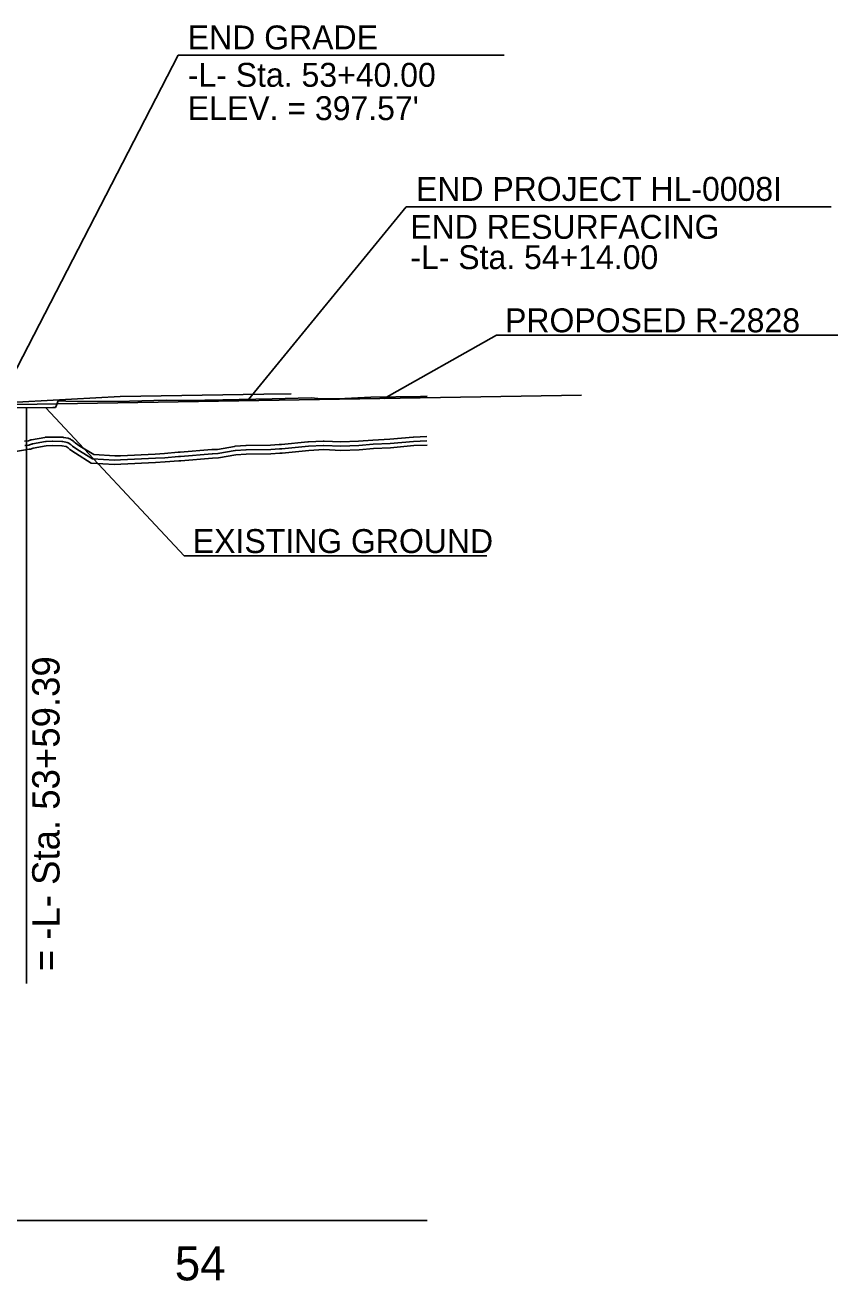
# Model space of a CAD drawing. Extents: x 1625686 to 1640492, y 1161393 to 1175642.
# Drawn here: x 1634553 to 1634790.9, y 1174893.1 to 1175260.6 of the extents above; entities that cross this region are included whole.
import ezdxf

# ---------------------------------------------------------------- set-up
doc = ezdxf.new("R2010")
doc.units = 0
for name, color, linetype in [('Exist Profile Cell', 7, 'Continuous'), ('Exist Vertical Profile Ground Line', 7, 'Continuous'), ('Exist Vertical Profile Horizontal Axis Label Major', 7, 'Continuous'), ('Prop PFL Text', 7, 'Continuous'), ('Prop VPI Label', 7, 'Continuous'), ('Scratch_Level_1', 7, 'Continuous'), ('Scratch_Level_3', 7, 'Continuous'), ('Scratch_Level_5', 7, 'Continuous'), ('Scratch_Level_7', 7, 'Continuous')]:
    doc.layers.add(name, color=color, linetype=linetype)

msp = doc.modelspace()

# ---------------------------------------------------------------- linework, layer by layer
at = {"layer": 'Exist Profile Cell'}
msp.add_line((1630204.31, 1174910.79), (1634670.63, 1174910.79), dxfattribs=at)
at = {"layer": 'Exist Vertical Profile Ground Line'}
msp.add_lwpolyline([(1634549.61, 1175148.68), (1634561.05, 1175148.7), (1634561.81, 1175148.73), (1634562.13, 1175149.43), (1634562.61, 1175150.67), (1634564.92, 1175150.56), (1634581.92, 1175150.48), (1634583.54, 1175150.64), (1634594.21, 1175150.87), (1634600.26, 1175150.79), (1634610.8, 1175150.96), (1634625.27, 1175151.27), (1634636.75, 1175151.62), (1634639.64, 1175151.3), (1634644.68, 1175151.25), (1634654.19, 1175151.73), (1634668.69, 1175151.94), (1634670.63, 1175152.03)], dxfattribs=at)
at = {"layer": 'Prop PFL Text'}
msp.add_line((1634553.35, 1174980.21), (1634553.35, 1175148.69), dxfattribs=at)
at = {"layer": 'Prop VPI Label'}
for p, q in [((1634545.73, 1175151), (1634597.75, 1175251.82)), ((1634597.75, 1175251.82), (1634693.23, 1175251.82)), ((1634618.31, 1175151.12), (1634664.56, 1175207.49)), ((1634664.56, 1175207.49), (1634788.92, 1175207.49)), ((1634599.55, 1175105.35), (1634558.98, 1175148.69)), ((1634688.15, 1175105.35), (1634599.55, 1175105.35))]:
    msp.add_line(p, q, dxfattribs=at)
at = {"layer": 'Scratch_Level_1'}
for p, q in [((1634554.86, 1175139.31), (1634558.71, 1175139.99)), ((1634555.07, 1175138.08), (1634558.92, 1175138.76)), ((1634559.04, 1175140.03), (1634560.82, 1175140.1)), ((1634559.09, 1175138.78), (1634560.87, 1175138.85)), ((1634560.93, 1175138.85), (1634563.74, 1175138.81)), ((1634560.95, 1175140.1), (1634563.76, 1175140.06)), ((1634563.98, 1175138.79), (1634565.26, 1175138.52)), ((1634564.23, 1175140.01), (1634565.52, 1175139.74)), ((1634566.48, 1175139.31), (1634567, 1175138.94)), ((1634635.9, 1175138.7), (1634640.26, 1175138.91)), ((1634666.64, 1175140.07), (1634670.52, 1175140.25)), ((1634666.7, 1175138.82), (1634670.58, 1175139)), ((1634565.75, 1175138.31), (1634566.27, 1175137.93)), ((1634614.5, 1175137.4), (1634617.53, 1175137.59)), ((1634614.58, 1175136.15), (1634617.61, 1175136.34)), ((1634635.96, 1175137.45), (1634640.32, 1175137.66))]:
    msp.add_line(p, q, dxfattribs=at)
for points in [[(1634552.82, 1175138.89), (1634553.83, 1175139), (1634553.92, 1175139.01), (1634554.44, 1175139.2)], [(1634567.28, 1175138.7), (1634567.59, 1175138.4), (1634569.02, 1175137.45), (1634573.07, 1175134.94), (1634579.19, 1175134.58), (1634580.84, 1175134.64), (1634591.01, 1175135.12), (1634593.78, 1175135.3), (1634597.78, 1175135.65)], [(1634627.38, 1175137.87), (1634628.03, 1175137.9), (1634635.76, 1175138.69)], [(1634640.52, 1175138.91), (1634645.37, 1175138.65), (1634650.58, 1175138.9), (1634654.71, 1175139.23)], [(1634654.8, 1175139.23), (1634659.73, 1175139.45), (1634666.53, 1175140.07)], [(1634654.85, 1175137.98), (1634659.81, 1175138.21), (1634666.65, 1175138.82)], [(1634552.95, 1175137.64), (1634554.01, 1175137.76), (1634554.25, 1175137.8), (1634554.87, 1175138.02)], [(1634566.4, 1175137.81), (1634566.8, 1175137.42), (1634568.35, 1175136.4), (1634572.68, 1175133.71), (1634579.17, 1175133.33), (1634580.89, 1175133.39), (1634591.08, 1175133.87), (1634593.88, 1175134.05), (1634597.89, 1175134.41)], [(1634597.9, 1175135.66), (1634598.35, 1175135.68), (1634607.61, 1175136.43)], [(1634597.95, 1175134.41), (1634598.42, 1175134.43), (1634607.71, 1175135.18)], [(1634607.74, 1175136.44), (1634609.29, 1175136.48), (1634614.21, 1175137.37)], [(1634607.77, 1175135.19), (1634609.42, 1175135.24), (1634614.43, 1175136.14)], [(1634617.65, 1175137.59), (1634624.82, 1175137.71), (1634627.34, 1175137.87)], [(1634617.67, 1175136.34), (1634624.87, 1175136.46), (1634627.42, 1175136.62)], [(1634627.44, 1175136.62), (1634628.12, 1175136.65), (1634635.89, 1175137.45)], [(1634640.45, 1175137.66), (1634645.36, 1175137.4), (1634650.66, 1175137.65), (1634654.81, 1175137.98)]]:
    msp.add_lwpolyline(points, dxfattribs=at)
for centre, radius, start, end in [((1634555.29, 1175136.85), 2.5, 100.0506, 109.9245), ((1634559.14, 1175137.53), 2.5, 92.2901, 100.0506), ((1634559.14, 1175137.53), 1.25, 92.2901, 100.0506), ((1634560.92, 1175137.6), 2.5, 89.1756, 92.2901), ((1634560.92, 1175137.6), 1.25, 89.1756, 92.2901), ((1634563.72, 1175137.56), 1.25, 78.3394, 89.1756), ((1634563.72, 1175137.56), 2.5, 78.3394, 89.1756), ((1634565.01, 1175137.3), 1.25, 53.8707, 78.3394), ((1634565.01, 1175137.3), 2.5, 53.8707, 78.3394), ((1634565.53, 1175136.92), 2.5, 45.5192, 53.8707), ((1634636.02, 1175136.2), 2.5, 92.7148, 95.8426), ((1634640.38, 1175136.41), 2.5, 86.9318, 92.7148), ((1634654.91, 1175136.74), 2.5, 92.5694, 94.609), ((1634666.76, 1175137.58), 2.5, 92.5786, 95.1312), ((1634666.76, 1175137.58), 1.25, 92.5786, 95.1312), ((1634553.08, 1175136.4), 1.25, 96.1835, 99.9774), ((1634555.29, 1175136.85), 1.25, 100.0506, 109.9245), ((1634565.53, 1175136.92), 1.25, 45.5192, 53.8707), ((1634598, 1175133.16), 2.5, 92.1129, 95.0088), ((1634607.81, 1175133.94), 2.5, 91.7402, 94.6531), ((1634607.81, 1175133.94), 1.25, 91.7402, 94.6531), ((1634614.65, 1175134.91), 2.5, 93.5573, 100.1635), ((1634614.65, 1175134.91), 1.25, 93.5573, 100.1635), ((1634617.69, 1175135.09), 2.5, 90.9471, 93.5573), ((1634617.69, 1175135.09), 1.25, 90.9471, 93.5573), ((1634627.5, 1175135.37), 2.5, 92.7689, 93.505), ((1634627.5, 1175135.37), 1.25, 92.7689, 93.505), ((1634636.02, 1175136.2), 1.25, 92.7148, 95.8426), ((1634640.38, 1175136.41), 1.25, 86.9318, 92.7148), ((1634654.91, 1175136.74), 1.25, 92.5694, 94.609), ((1634598, 1175133.16), 1.25, 92.1129, 95.0088)]:
    msp.add_arc(centre, radius, start, end, dxfattribs=at)
at = {"layer": 'Scratch_Level_3'}
msp.add_lwpolyline([(1634530.81, 1175149.25), (1634580.81, 1175151.93), (1634622.81, 1175152.63), (1634630.81, 1175152.76)], dxfattribs=at)
at = {"layer": 'Scratch_Level_5'}
msp.add_lwpolyline([(1634548.36, 1175135.57), (1634553.08, 1175136.4), (1634554.18, 1175136.52), (1634554.57, 1175136.59), (1634555.29, 1175136.85), (1634559.14, 1175137.53), (1634560.92, 1175137.6), (1634563.72, 1175137.56), (1634565.01, 1175137.3), (1634565.53, 1175136.92), (1634566.01, 1175136.45), (1634567.68, 1175135.35), (1634572.29, 1175132.48), (1634579.16, 1175132.08), (1634580.95, 1175132.15), (1634591.15, 1175132.62), (1634593.98, 1175132.81), (1634598, 1175133.16), (1634598.5, 1175133.18), (1634607.81, 1175133.94), (1634609.55, 1175133.99), (1634614.65, 1175134.91), (1634617.69, 1175135.09), (1634624.92, 1175135.21), (1634627.5, 1175135.37), (1634628.22, 1175135.41), (1634636.02, 1175136.2), (1634640.38, 1175136.41), (1634645.36, 1175136.14), (1634650.74, 1175136.4), (1634654.91, 1175136.74), (1634659.9, 1175136.96), (1634666.76, 1175137.58), (1634670.63, 1175137.75)], dxfattribs=at)
at = {"layer": 'Scratch_Level_7'}
for p, q in [((1634690.95, 1175169.95), (1634658.1, 1175151.36)), ((1634790.92, 1175169.95), (1634690.95, 1175169.95)), ((1634504.31, 1175148.81), (1634715.81, 1175152.31))]:
    msp.add_line(p, q, dxfattribs=at)

# ---------------------------------------------------------------- texts
at = {"layer": 'Exist Vertical Profile Horizontal Axis Label Major'}
msp.add_text('54', height=10, dxfattribs=at).set_placement((1634596.77, 1174893.29))
at = {"layer": 'Prop PFL Text'}
msp.add_text('= -L- Sta. 53+59.39', height=8, rotation=90, dxfattribs=at).set_placement((1634563.03, 1174983.76))
at = {"layer": 'Prop VPI Label'}
for s, p in [('END GRADE', (1634600.59, 1175253.54)), ('-L- Sta. 53+40.00', (1634600.59, 1175242.6)), ("ELEV. = 397.57'", (1634600.59, 1175232.85)), ('END PROJECT HL-0008I', (1634667.4, 1175209.21)), ('END RESURFACING', (1634665.74, 1175198.11)), ('-L- Sta. 54+14.00', (1634665.74, 1175189.24)), ('EXISTING GROUND', (1634602.07, 1175106.15))]:
    msp.add_text(s, height=7, dxfattribs=at).set_placement(p)
at = {"layer": 'Scratch_Level_7'}
msp.add_text('PROPOSED R-2828', height=7, dxfattribs=at).set_placement((1634693.48, 1175170.75))

doc.saveas('drawing.dxf')
